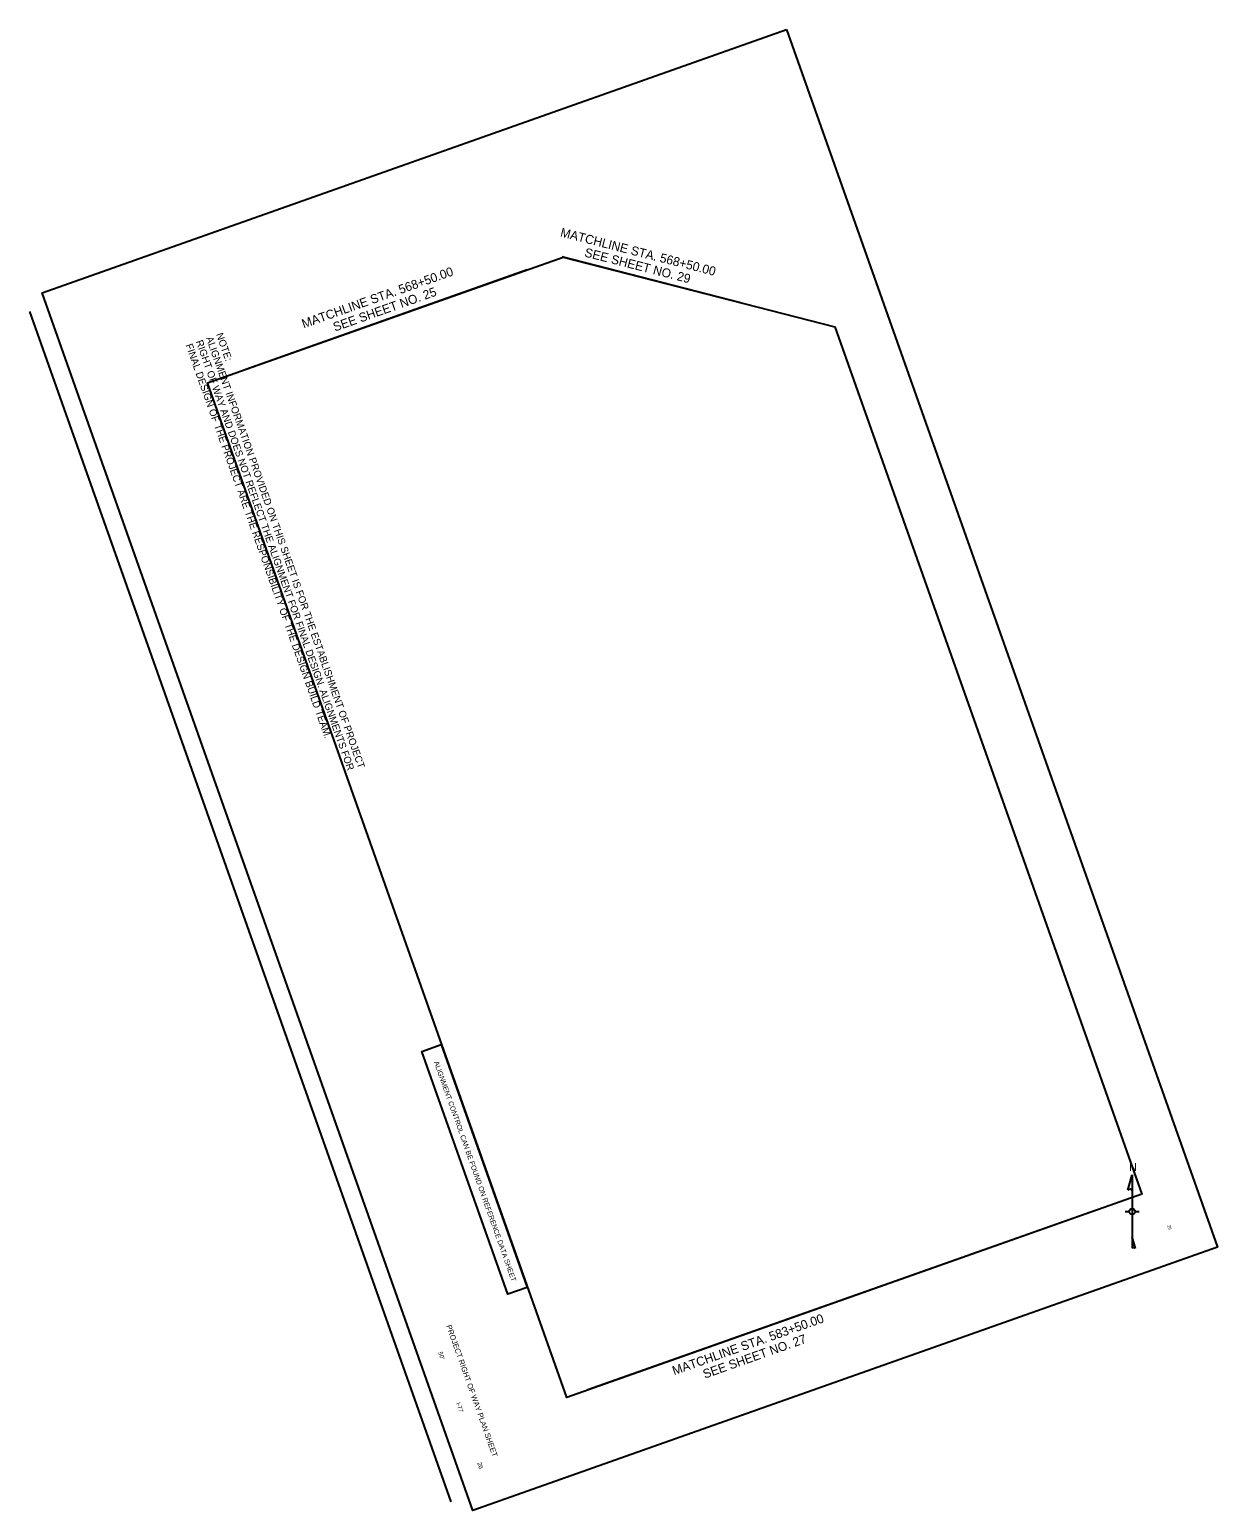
# Model space of a CAD drawing. Extents: x 2005690 to 2007344, y 1134707 to 1136771.
import ezdxf

# ---------------------------------------------------------------- set-up
doc = ezdxf.new("R2010")
doc.units = 0
for name, color, linetype in [('North Arrow', 7, 'Continuous'), ('RD_SHT_IplotShp', 7, 'Continuous'), ('RD_SHT_MatchLine', 7, 'Continuous'), ('RD_SHT_Misc1', 7, 'Continuous'), ('RD_SHT_ShtClip', 7, 'Continuous'), ('RD_SHT_TX', 7, 'Continuous')]:
    doc.layers.add(name, color=color, linetype=linetype)

msp = doc.modelspace()

# ---------------------------------------------------------------- linework, layer by layer
at = {"layer": 'North Arrow'}
for p, q in [((2007219.6, 1135153.3), (2007225.5, 1135174.3)), ((2007225.5, 1135174.3), (2007225.5, 1135152.2)), ((2007225.5, 1135174.3), (2007225.5, 1135072.1)), ((2007215.8, 1135123.2), (2007221.5, 1135123.2)), ((2007229.5, 1135123.2), (2007235.2, 1135123.2)), ((2007225.5, 1135087.9), (2007225.5, 1135072.1)), ((2007230.1, 1135071.8), (2007225.5, 1135087.9))]:
    msp.add_line(p, q, dxfattribs=at)
msp.add_circle((2007225.5, 1135123.2), 4.02, dxfattribs=at)
for centre, radius, start, end in [((2007222.2, 1135150.8), 3.59, 22.3707, 136.1387), ((2007227.7, 1135069.6), 3.3, 43.3397, 130.5607)]:
    msp.add_arc(centre, radius, start, end, dxfattribs=at)
at = {"layer": 'RD_SHT_IplotShp'}
msp.add_lwpolyline([(2006743.9, 1136770.6), (2007344.2, 1135073.6), (2006307.2, 1134706.8), (2005706.9, 1136403.7)], close=True, dxfattribs=at)
at = {"layer": 'RD_SHT_MatchLine'}
for p, q in [((2006382.6, 1136435.7), (2005990.6, 1136297)), ((2006680.4, 1136389.9), (2006431.3, 1136453.8)), ((2007174.3, 1135124.7), (2006467.3, 1134874.6))]:
    msp.add_line(p, q, dxfattribs=at)
at = {"layer": 'RD_SHT_ShtClip'}
msp.add_lwpolyline([(2005937.5, 1136278.3), (2006432.7, 1136453.4), (2006811.5, 1136356.3), (2007239.1, 1135147.6), (2006437.8, 1134864.1)], close=True, dxfattribs=at)
at = {"layer": 'RD_SHT_TX'}
msp.add_line((2005689.5, 1136377.8), (2006276.5, 1134718.6), dxfattribs=at)
msp.add_lwpolyline([(2006262.8, 1135356), (2006382.6, 1135017.4), (2006355.8, 1135007.9), (2006236, 1135346.5)], close=True, dxfattribs=at)

# ---------------------------------------------------------------- texts
at = {"layer": 'North Arrow'}
msp.add_text('N', height=11.1, dxfattribs=at).set_placement((2007221.4, 1135179.8))
at = {"layer": 'RD_SHT_MatchLine'}
for s, rotation, p in [('MATCHLINE STA. 568+50.00', 345.6281, (2006428, 1136482.5)), ('SEE SHEET NO. 29', 345.6281, (2006461.7, 1136454.5)), ('MATCHLINE STA. 568+50.00', 19.482, (2006071.3, 1136354.2)), ('SEE SHEET NO. 25', 19.482, (2006114.9, 1136349.7)), ('MATCHLINE STA. 583+50.00', 19.482, (2006587.4, 1134895.1)), ('SEE SHEET NO. 27', 19.482, (2006630.1, 1134890.3))]:
    msp.add_text(s, height=12.5, rotation=rotation, dxfattribs=at).set_placement(p)
at = {"layer": 'RD_SHT_Misc1'}
for s, p in [('FINAL DESIGN OF THE PROJECT ARE THE RESPONSIBILITY OF THE DESIGN BUILD TEAM.', (2005906.7, 1136330.9)), ('RIGHT OF WAY AND DOES NOT REFLECT THE ALIGNMENT FOR FINAL DESIGN. ALIGNMENTS FOR', (2005920.9, 1136335.9)), ('ALIGNMENT INFORMATION PROVIDED ON THIS SHEET IS FOR THE ESTABLISHMENT OF PROJECT', (2005935, 1136340.9)), ('NOTE:', (2005949.1, 1136345.9))]:
    msp.add_text(s, height=10, rotation=289.482, dxfattribs=at).set_placement(p)
at = {"layer": 'RD_SHT_TX'}
for s, height, p in [('ALIGNMENT CONTROL CAN BE FOUND ON REFERENCE DATA SHEET', 7, (2006252.7, 1135331.4)), ('26', 4.5, (2007274.2, 1135103.7)), ('PROJECT RIGHT OF WAY PLAN SHEET', 7.5, (2006269.8, 1134963.9)), ("50'", 6, (2006258.6, 1134926.7)), ('I-77', 6, (2006283.6, 1134856.1)), ('26', 6, (2006313, 1134772.8))]:
    msp.add_text(s, height=height, rotation=289.482, dxfattribs=at).set_placement(p)

doc.saveas('drawing.dxf')
